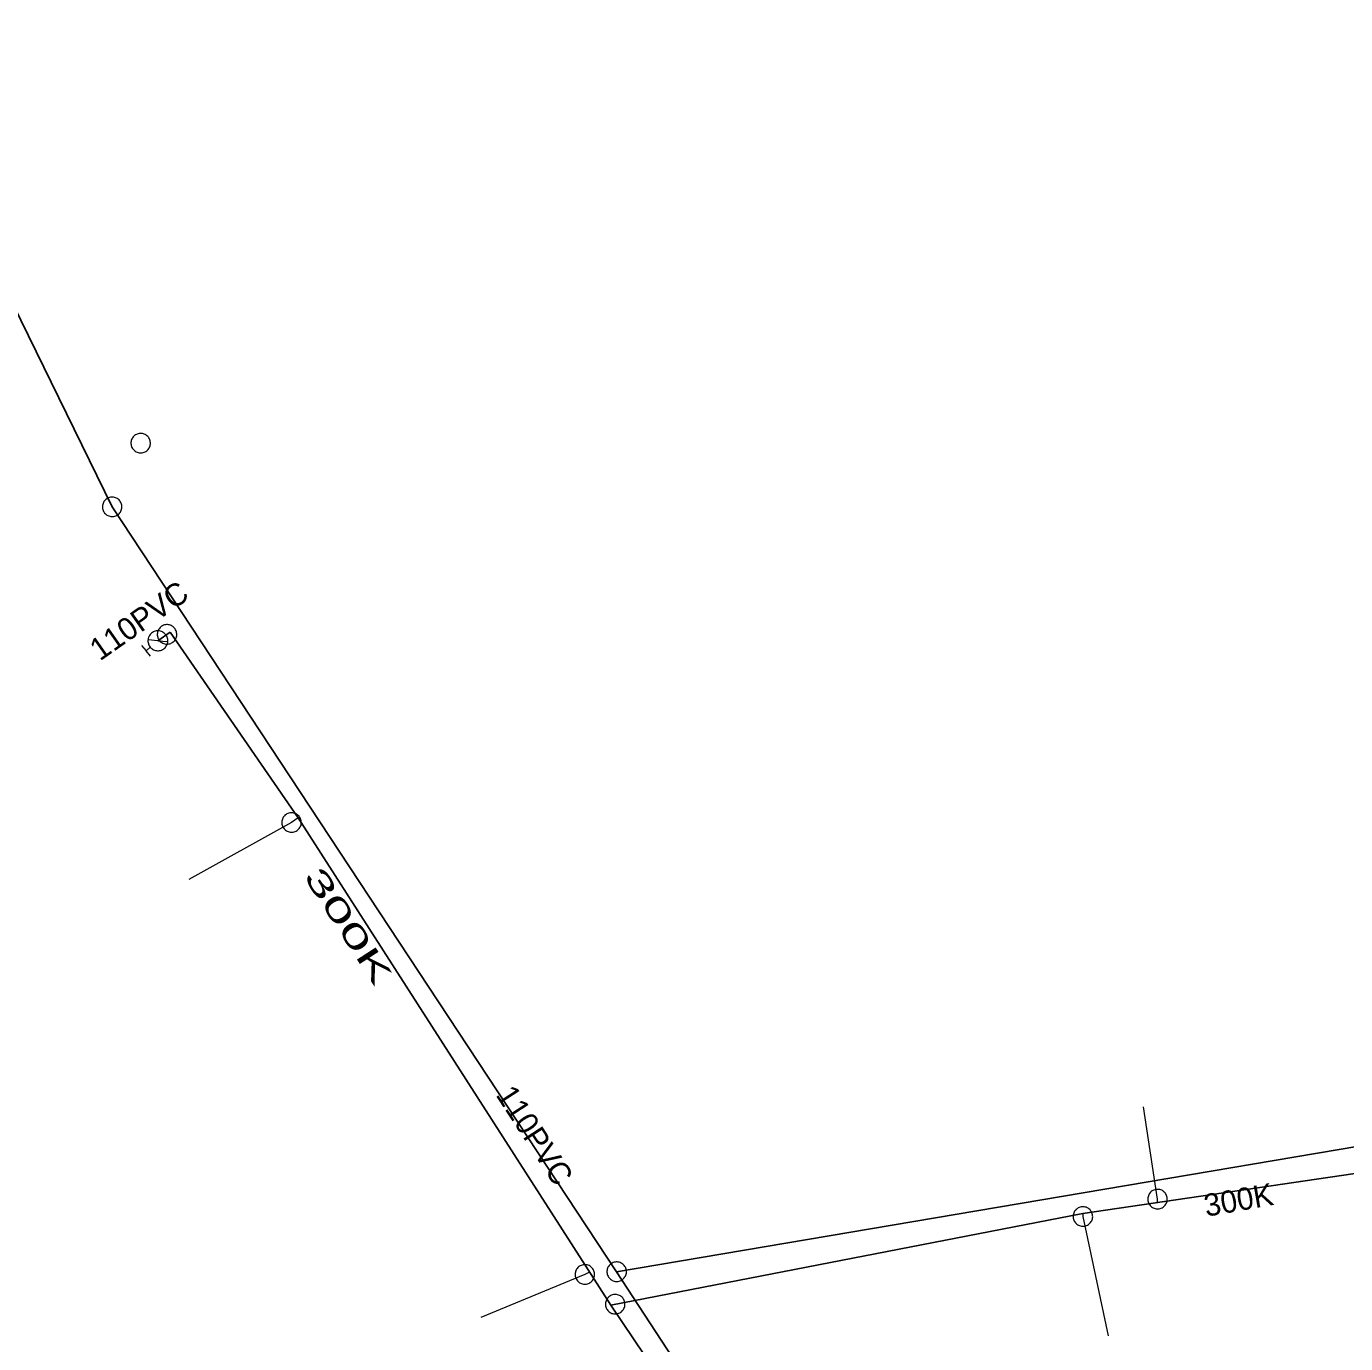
# Model space of a CAD drawing. Extents: x -741806 to -738704, y -1059275 to -1055387.
# Drawn here: x -740655.8 to -740596.6, y -1057415.2 to -1057356.1 of the extents above; entities that cross this region are included whole.
import ezdxf

# ---------------------------------------------------------------- set-up
doc = ezdxf.new("R2010")
doc.units = 0
doc.header["$LTSCALE"] = 0.4
for name, color, linetype, lineweight in [('2', 7, 'Continuous', 25), ('21', 7, 'Continuous', 13), ('3', 7, 'Continuous', 13), ('50', 7, 'Continuous', 13), ('51', 7, 'Continuous', 13), ('52', 7, 'Continuous', 25)]:
    doc.layers.add(name, color=color, linetype=linetype, lineweight=lineweight)
doc.layers.add('5', color=7, linetype='Continuous')
doc.layers.add('53', color=7, linetype='Continuous')

msp = doc.modelspace()

# ---------------------------------------------------------------- linework, layer by layer
at = {"layer": '2'}
for points in [[(-740629.3, -1057411.95), (-740651.94, -1057377.629), (-740665.26, -1057350.399)], [(-740483.87, -1057386.129), (-740524.48, -1057393.58), (-740573.109, -1057402.44), (-740629.3, -1057411.95)], [(-740551.37, -1057549.6), (-740573.489, -1057504.53), (-740597.07, -1057461.26), (-740629.3, -1057411.95)]]:
    msp.add_lwpolyline(points, dxfattribs=at)
at = {"layer": '21'}
for points in [[(-740643.596, -1057391.587), (-740643.89, -1057391.79), (-740648.499, -1057394.343)], [(-740605.036, -1057408.848), (-740605.03, -1057408.69), (-740605.666, -1057404.549)], [(-740608.386, -1057409.341), (-740608.379, -1057409.47), (-740607.25, -1057414.818)], [(-740630.515, -1057411.972), (-740630.73, -1057412.07), (-740635.388, -1057414.007)]]:
    msp.add_lwpolyline(points, dxfattribs=at)
at = {"layer": '3'}
for points in [[(-740650.892, -1057374.399), (-740650.929, -1057374.425), (-740650.963, -1057374.455), (-740650.995, -1057374.489), (-740651.022, -1057374.525), (-740651.045, -1057374.565), (-740651.065, -1057374.607), (-740651.079, -1057374.65), (-740651.09, -1057374.694), (-740651.095, -1057374.74), (-740651.096, -1057374.785), (-740651.092, -1057374.831), (-740651.083, -1057374.877), (-740651.069, -1057374.92), (-740651.052, -1057374.962), (-740651.029, -1057375.002), (-740651.003, -1057375.04), (-740650.972, -1057375.074), (-740650.939, -1057375.105), (-740650.902, -1057375.132), (-740650.862, -1057375.156), (-740650.821, -1057375.175), (-740650.779, -1057375.189), (-740650.733, -1057375.2), (-740650.688, -1057375.206), (-740650.642, -1057375.206), (-740650.596, -1057375.201), (-740650.552, -1057375.193), (-740650.507, -1057375.179), (-740650.465, -1057375.161), (-740650.425, -1057375.139), (-740650.388, -1057375.113), (-740650.354, -1057375.083), (-740650.322, -1057375.049), (-740650.295, -1057375.012), (-740650.272, -1057374.973), (-740650.252, -1057374.931), (-740650.238, -1057374.888), (-740650.228, -1057374.843), (-740650.223, -1057374.798), (-740650.222, -1057374.753), (-740650.226, -1057374.707), (-740650.234, -1057374.661), (-740650.248, -1057374.618), (-740650.266, -1057374.576), (-740650.288, -1057374.536), (-740650.315, -1057374.498), (-740650.345, -1057374.464), (-740650.378, -1057374.433), (-740650.415, -1057374.405), (-740650.455, -1057374.382), (-740650.496, -1057374.363), (-740650.539, -1057374.348), (-740650.584, -1057374.338), (-740650.629, -1057374.332), (-740650.676, -1057374.332), (-740650.722, -1057374.336), (-740650.766, -1057374.345), (-740650.81, -1057374.359), (-740650.852, -1057374.377), (-740650.892, -1057374.398)], [(-740652.18, -1057377.263), (-740652.216, -1057377.29), (-740652.25, -1057377.321), (-740652.281, -1057377.355), (-740652.307, -1057377.392), (-740652.33, -1057377.432), (-740652.349, -1057377.474), (-740652.362, -1057377.518), (-740652.372, -1057377.563), (-740652.375, -1057377.608), (-740652.375, -1057377.654), (-740652.37, -1057377.699), (-740652.361, -1057377.745), (-740652.346, -1057377.787), (-740652.328, -1057377.829), (-740652.304, -1057377.869), (-740652.277, -1057377.906), (-740652.245, -1057377.939), (-740652.212, -1057377.97), (-740652.174, -1057377.997), (-740652.134, -1057378.019), (-740652.092, -1057378.037), (-740652.05, -1057378.051), (-740652.004, -1057378.06), (-740651.959, -1057378.065), (-740651.912, -1057378.065), (-740651.867, -1057378.059), (-740651.823, -1057378.05), (-740651.779, -1057378.035), (-740651.737, -1057378.016), (-740651.698, -1057377.992), (-740651.661, -1057377.966), (-740651.627, -1057377.935), (-740651.596, -1057377.901), (-740651.57, -1057377.863), (-740651.548, -1057377.824), (-740651.529, -1057377.782), (-740651.516, -1057377.738), (-740651.506, -1057377.692), (-740651.502, -1057377.648), (-740651.502, -1057377.602), (-740651.507, -1057377.557), (-740651.517, -1057377.511), (-740651.531, -1057377.468), (-740651.55, -1057377.427), (-740651.573, -1057377.387), (-740651.6, -1057377.35), (-740651.631, -1057377.316), (-740651.665, -1057377.286), (-740651.703, -1057377.259), (-740651.743, -1057377.237), (-740651.785, -1057377.219), (-740651.828, -1057377.204), (-740651.873, -1057377.196), (-740651.919, -1057377.191), (-740651.965, -1057377.191), (-740652.011, -1057377.196), (-740652.055, -1057377.206), (-740652.099, -1057377.221), (-740652.14, -1057377.24), (-740652.179, -1057377.262)], [(-740629.539, -1057411.583), (-740629.575, -1057411.61), (-740629.609, -1057411.64), (-740629.64, -1057411.675), (-740629.666, -1057411.711), (-740629.689, -1057411.751), (-740629.708, -1057411.794), (-740629.721, -1057411.837), (-740629.731, -1057411.882), (-740629.735, -1057411.927), (-740629.735, -1057411.973), (-740629.73, -1057412.019), (-740629.721, -1057412.064), (-740629.706, -1057412.107), (-740629.688, -1057412.149), (-740629.665, -1057412.188), (-740629.638, -1057412.226), (-740629.607, -1057412.259), (-740629.573, -1057412.29), (-740629.536, -1057412.317), (-740629.496, -1057412.339), (-740629.454, -1057412.357), (-740629.411, -1057412.371), (-740629.366, -1057412.381), (-740629.321, -1057412.386), (-740629.274, -1057412.386), (-740629.229, -1057412.38), (-740629.184, -1057412.371), (-740629.14, -1057412.357), (-740629.099, -1057412.338), (-740629.059, -1057412.314), (-740629.023, -1057412.288), (-740628.989, -1057412.258), (-740628.958, -1057412.223), (-740628.931, -1057412.185), (-740628.908, -1057412.147), (-740628.889, -1057412.104), (-740628.876, -1057412.061), (-740628.866, -1057412.015), (-740628.862, -1057411.971), (-740628.862, -1057411.925), (-740628.867, -1057411.879), (-740628.876, -1057411.834), (-740628.89, -1057411.791), (-740628.909, -1057411.749), (-740628.932, -1057411.71), (-740628.959, -1057411.672), (-740628.99, -1057411.638), (-740629.024, -1057411.608), (-740629.062, -1057411.581), (-740629.102, -1057411.559), (-740629.143, -1057411.54), (-740629.187, -1057411.526), (-740629.232, -1057411.517), (-740629.277, -1057411.512), (-740629.323, -1057411.512), (-740629.369, -1057411.517), (-740629.413, -1057411.527), (-740629.457, -1057411.541), (-740629.499, -1057411.56), (-740629.538, -1057411.582)]]:
    msp.add_lwpolyline(points, dxfattribs=at)
at = {"layer": '50'}
for p, q in [((-740650.617, -1057383.85), (-740650.42, -1057384.085)), ((-740650.228, -1057383.924), (-740650.42, -1057384.085)), ((-740649.886, -1057383.636), (-740650.328, -1057383.595)), ((-740649.886, -1057383.636), (-740649.439, -1057383.675)), ((-740650.222, -1057384.321), (-740650.42, -1057384.085))]:
    msp.add_line(p, q, dxfattribs=at)
msp.add_lwpolyline([(-740650.168, -1057383.293), (-740650.204, -1057383.327), (-740650.236, -1057383.36), (-740650.263, -1057383.4), (-740650.285, -1057383.44), (-740650.303, -1057383.481), (-740650.317, -1057383.528), (-740650.326, -1057383.572), (-740650.331, -1057383.62), (-740650.332, -1057383.666), (-740650.324, -1057383.712), (-740650.315, -1057383.758), (-740650.302, -1057383.803), (-740650.28, -1057383.845), (-740650.256, -1057383.885), (-740650.229, -1057383.922), (-740650.197, -1057383.955), (-740650.164, -1057383.987), (-740650.125, -1057384.014), (-740650.084, -1057384.036), (-740650.04, -1057384.056), (-740649.996, -1057384.069), (-740649.95, -1057384.079), (-740649.904, -1057384.083), (-740649.858, -1057384.082), (-740649.81, -1057384.077), (-740649.765, -1057384.068), (-740649.722, -1057384.052), (-740649.677, -1057384.034), (-740649.639, -1057384.008), (-740649.6, -1057383.983), (-740649.565, -1057383.95), (-740649.535, -1057383.914), (-740649.509, -1057383.878), (-740649.484, -1057383.836), (-740649.467, -1057383.793), (-740649.452, -1057383.749), (-740649.444, -1057383.703), (-740649.438, -1057383.656), (-740649.439, -1057383.608), (-740649.445, -1057383.563), (-740649.456, -1057383.516), (-740649.472, -1057383.473), (-740649.488, -1057383.431), (-740649.514, -1057383.389), (-740649.541, -1057383.351), (-740649.573, -1057383.318), (-740649.609, -1057383.288), (-740649.647, -1057383.26), (-740649.687, -1057383.237), (-740649.731, -1057383.218), (-740649.774, -1057383.205), (-740649.821, -1057383.195), (-740649.866, -1057383.191), (-740649.912, -1057383.19), (-740649.959, -1057383.198), (-740650.005, -1057383.206), (-740650.05, -1057383.221), (-740650.091, -1057383.242), (-740650.131, -1057383.266)], close=True, dxfattribs=at)
at = {"layer": '51'}
for points in [[(-740649.757, -1057383.014), (-740649.79, -1057383.045), (-740649.82, -1057383.079), (-740649.847, -1057383.117), (-740649.869, -1057383.157), (-740649.887, -1057383.199), (-740649.901, -1057383.243), (-740649.909, -1057383.288), (-740649.913, -1057383.334), (-740649.912, -1057383.379), (-740649.906, -1057383.424), (-740649.896, -1057383.469), (-740649.882, -1057383.513), (-740649.862, -1057383.555), (-740649.839, -1057383.594), (-740649.811, -1057383.63), (-740649.78, -1057383.664), (-740649.745, -1057383.694), (-740649.708, -1057383.72), (-740649.667, -1057383.742), (-740649.625, -1057383.76), (-740649.581, -1057383.773), (-740649.537, -1057383.783), (-740649.491, -1057383.786), (-740649.445, -1057383.786), (-740649.399, -1057383.78), (-740649.355, -1057383.769), (-740649.312, -1057383.755), (-740649.27, -1057383.735), (-740649.231, -1057383.711), (-740649.194, -1057383.684), (-740649.161, -1057383.653), (-740649.131, -1057383.619), (-740649.105, -1057383.58), (-740649.083, -1057383.541), (-740649.065, -1057383.499), (-740649.051, -1057383.455), (-740649.043, -1057383.41), (-740649.038, -1057383.364), (-740649.04, -1057383.319), (-740649.045, -1057383.273), (-740649.055, -1057383.228), (-740649.07, -1057383.185), (-740649.09, -1057383.144), (-740649.113, -1057383.104), (-740649.141, -1057383.068), (-740649.172, -1057383.034), (-740649.207, -1057383.004), (-740649.243, -1057382.978), (-740649.284, -1057382.956), (-740649.327, -1057382.938), (-740649.37, -1057382.925), (-740649.415, -1057382.915), (-740649.461, -1057382.912), (-740649.506, -1057382.912), (-740649.552, -1057382.918), (-740649.597, -1057382.928), (-740649.639, -1057382.943), (-740649.682, -1057382.963), (-740649.72, -1057382.986), (-740649.756, -1057383.014)], [(-740644.17, -1057391.454), (-740644.203, -1057391.485), (-740644.233, -1057391.519), (-740644.26, -1057391.557), (-740644.282, -1057391.597), (-740644.3, -1057391.639), (-740644.314, -1057391.683), (-740644.322, -1057391.728), (-740644.326, -1057391.774), (-740644.325, -1057391.819), (-740644.319, -1057391.864), (-740644.309, -1057391.909), (-740644.295, -1057391.953), (-740644.275, -1057391.995), (-740644.252, -1057392.034), (-740644.224, -1057392.07), (-740644.193, -1057392.104), (-740644.158, -1057392.134), (-740644.121, -1057392.16), (-740644.08, -1057392.182), (-740644.038, -1057392.2), (-740643.994, -1057392.213), (-740643.95, -1057392.223), (-740643.904, -1057392.226), (-740643.858, -1057392.226), (-740643.812, -1057392.22), (-740643.768, -1057392.209), (-740643.725, -1057392.195), (-740643.683, -1057392.175), (-740643.644, -1057392.151), (-740643.607, -1057392.124), (-740643.574, -1057392.093), (-740643.544, -1057392.059), (-740643.518, -1057392.02), (-740643.496, -1057391.981), (-740643.478, -1057391.939), (-740643.464, -1057391.895), (-740643.456, -1057391.85), (-740643.451, -1057391.804), (-740643.453, -1057391.759), (-740643.458, -1057391.713), (-740643.468, -1057391.668), (-740643.483, -1057391.625), (-740643.503, -1057391.584), (-740643.526, -1057391.544), (-740643.554, -1057391.508), (-740643.585, -1057391.474), (-740643.62, -1057391.444), (-740643.656, -1057391.418), (-740643.697, -1057391.396), (-740643.74, -1057391.378), (-740643.783, -1057391.365), (-740643.828, -1057391.355), (-740643.874, -1057391.352), (-740643.919, -1057391.352), (-740643.965, -1057391.358), (-740644.01, -1057391.368), (-740644.052, -1057391.383), (-740644.095, -1057391.403), (-740644.133, -1057391.426), (-740644.169, -1057391.454)], [(-740605.31, -1057408.354), (-740605.343, -1057408.385), (-740605.373, -1057408.419), (-740605.4, -1057408.457), (-740605.422, -1057408.497), (-740605.44, -1057408.539), (-740605.454, -1057408.583), (-740605.462, -1057408.628), (-740605.466, -1057408.674), (-740605.465, -1057408.719), (-740605.459, -1057408.764), (-740605.449, -1057408.809), (-740605.435, -1057408.853), (-740605.415, -1057408.895), (-740605.392, -1057408.934), (-740605.364, -1057408.97), (-740605.333, -1057409.004), (-740605.298, -1057409.034), (-740605.261, -1057409.06), (-740605.22, -1057409.082), (-740605.178, -1057409.1), (-740605.134, -1057409.113), (-740605.09, -1057409.123), (-740605.044, -1057409.126), (-740604.998, -1057409.126), (-740604.952, -1057409.12), (-740604.908, -1057409.109), (-740604.865, -1057409.095), (-740604.823, -1057409.075), (-740604.784, -1057409.051), (-740604.747, -1057409.024), (-740604.714, -1057408.993), (-740604.684, -1057408.959), (-740604.658, -1057408.92), (-740604.636, -1057408.881), (-740604.618, -1057408.839), (-740604.604, -1057408.795), (-740604.596, -1057408.75), (-740604.591, -1057408.704), (-740604.593, -1057408.659), (-740604.598, -1057408.613), (-740604.608, -1057408.568), (-740604.623, -1057408.525), (-740604.643, -1057408.484), (-740604.666, -1057408.444), (-740604.694, -1057408.408), (-740604.725, -1057408.374), (-740604.76, -1057408.344), (-740604.796, -1057408.318), (-740604.837, -1057408.296), (-740604.88, -1057408.278), (-740604.923, -1057408.265), (-740604.968, -1057408.255), (-740605.014, -1057408.252), (-740605.059, -1057408.252), (-740605.105, -1057408.258), (-740605.15, -1057408.268), (-740605.192, -1057408.283), (-740605.235, -1057408.303), (-740605.273, -1057408.326), (-740605.309, -1057408.354)], [(-740608.659, -1057409.134), (-740608.692, -1057409.165), (-740608.722, -1057409.199), (-740608.749, -1057409.237), (-740608.771, -1057409.277), (-740608.789, -1057409.319), (-740608.803, -1057409.363), (-740608.811, -1057409.408), (-740608.815, -1057409.454), (-740608.814, -1057409.499), (-740608.808, -1057409.544), (-740608.798, -1057409.589), (-740608.784, -1057409.633), (-740608.764, -1057409.675), (-740608.741, -1057409.714), (-740608.713, -1057409.75), (-740608.682, -1057409.784), (-740608.647, -1057409.814), (-740608.61, -1057409.84), (-740608.569, -1057409.862), (-740608.527, -1057409.88), (-740608.483, -1057409.893), (-740608.439, -1057409.903), (-740608.393, -1057409.906), (-740608.347, -1057409.906), (-740608.301, -1057409.9), (-740608.257, -1057409.889), (-740608.214, -1057409.875), (-740608.172, -1057409.855), (-740608.133, -1057409.831), (-740608.096, -1057409.804), (-740608.063, -1057409.773), (-740608.033, -1057409.739), (-740608.007, -1057409.7), (-740607.985, -1057409.661), (-740607.967, -1057409.619), (-740607.953, -1057409.575), (-740607.945, -1057409.53), (-740607.94, -1057409.484), (-740607.942, -1057409.439), (-740607.947, -1057409.393), (-740607.957, -1057409.348), (-740607.972, -1057409.305), (-740607.992, -1057409.264), (-740608.015, -1057409.224), (-740608.043, -1057409.188), (-740608.074, -1057409.154), (-740608.109, -1057409.124), (-740608.145, -1057409.098), (-740608.186, -1057409.076), (-740608.229, -1057409.058), (-740608.272, -1057409.045), (-740608.317, -1057409.035), (-740608.363, -1057409.032), (-740608.408, -1057409.032), (-740608.454, -1057409.038), (-740608.499, -1057409.048), (-740608.541, -1057409.063), (-740608.584, -1057409.083), (-740608.622, -1057409.106), (-740608.658, -1057409.134)], [(-740631.01, -1057411.734), (-740631.043, -1057411.765), (-740631.073, -1057411.799), (-740631.1, -1057411.837), (-740631.122, -1057411.877), (-740631.14, -1057411.919), (-740631.154, -1057411.963), (-740631.162, -1057412.008), (-740631.166, -1057412.054), (-740631.165, -1057412.099), (-740631.159, -1057412.144), (-740631.149, -1057412.189), (-740631.135, -1057412.233), (-740631.115, -1057412.275), (-740631.092, -1057412.314), (-740631.064, -1057412.35), (-740631.033, -1057412.384), (-740630.998, -1057412.414), (-740630.961, -1057412.44), (-740630.92, -1057412.462), (-740630.878, -1057412.48), (-740630.834, -1057412.493), (-740630.79, -1057412.503), (-740630.744, -1057412.506), (-740630.698, -1057412.506), (-740630.652, -1057412.5), (-740630.608, -1057412.489), (-740630.565, -1057412.475), (-740630.523, -1057412.455), (-740630.484, -1057412.431), (-740630.447, -1057412.404), (-740630.414, -1057412.373), (-740630.384, -1057412.339), (-740630.358, -1057412.3), (-740630.336, -1057412.261), (-740630.318, -1057412.219), (-740630.304, -1057412.175), (-740630.296, -1057412.13), (-740630.291, -1057412.084), (-740630.293, -1057412.039), (-740630.298, -1057411.993), (-740630.308, -1057411.948), (-740630.323, -1057411.905), (-740630.343, -1057411.864), (-740630.366, -1057411.824), (-740630.394, -1057411.788), (-740630.425, -1057411.754), (-740630.46, -1057411.724), (-740630.496, -1057411.698), (-740630.537, -1057411.676), (-740630.58, -1057411.658), (-740630.623, -1057411.645), (-740630.668, -1057411.635), (-740630.714, -1057411.632), (-740630.759, -1057411.632), (-740630.805, -1057411.638), (-740630.85, -1057411.648), (-740630.892, -1057411.663), (-740630.935, -1057411.683), (-740630.973, -1057411.706), (-740631.009, -1057411.734)], [(-740629.645, -1057413.071), (-740629.678, -1057413.102), (-740629.708, -1057413.136), (-740629.735, -1057413.174), (-740629.757, -1057413.214), (-740629.775, -1057413.256), (-740629.789, -1057413.3), (-740629.797, -1057413.345), (-740629.801, -1057413.391), (-740629.8, -1057413.436), (-740629.794, -1057413.481), (-740629.784, -1057413.526), (-740629.77, -1057413.57), (-740629.75, -1057413.612), (-740629.727, -1057413.651), (-740629.699, -1057413.687), (-740629.668, -1057413.721), (-740629.633, -1057413.751), (-740629.596, -1057413.777), (-740629.555, -1057413.799), (-740629.513, -1057413.817), (-740629.469, -1057413.83), (-740629.425, -1057413.84), (-740629.379, -1057413.843), (-740629.333, -1057413.843), (-740629.287, -1057413.837), (-740629.243, -1057413.826), (-740629.2, -1057413.812), (-740629.158, -1057413.792), (-740629.119, -1057413.768), (-740629.082, -1057413.741), (-740629.049, -1057413.71), (-740629.019, -1057413.676), (-740628.993, -1057413.637), (-740628.971, -1057413.598), (-740628.953, -1057413.556), (-740628.939, -1057413.512), (-740628.931, -1057413.467), (-740628.926, -1057413.421), (-740628.928, -1057413.376), (-740628.933, -1057413.33), (-740628.943, -1057413.285), (-740628.958, -1057413.242), (-740628.978, -1057413.201), (-740629.001, -1057413.161), (-740629.029, -1057413.125), (-740629.06, -1057413.091), (-740629.095, -1057413.061), (-740629.131, -1057413.035), (-740629.172, -1057413.013), (-740629.215, -1057412.995), (-740629.258, -1057412.982), (-740629.303, -1057412.972), (-740629.349, -1057412.969), (-740629.394, -1057412.969), (-740629.44, -1057412.975), (-740629.485, -1057412.985), (-740629.527, -1057413), (-740629.57, -1057413.02), (-740629.608, -1057413.043), (-740629.644, -1057413.071)]]:
    msp.add_lwpolyline(points, dxfattribs=at)
at = {"layer": '52'}
msp.add_line((-740649.339, -1057383.253), (-740649.89, -1057383.639), dxfattribs=at)
for points in [[(-740629.568, -1057413.446), (-740643.596, -1057391.587), (-740649.339, -1057383.253)], [(-740447.059, -1057384.081), (-740482.611, -1057386.857), (-740514.765, -1057392.747), (-740521.043, -1057394.158), (-740540.033, -1057397.307), (-740548.526, -1057398.619), (-740563.186, -1057401.392), (-740569.092, -1057402.71), (-740590.765, -1057406.389), (-740595.761, -1057407.486), (-740608.386, -1057409.341), (-740629.568, -1057413.446)], [(-740629.568, -1057413.446), (-740618.379, -1057430.067), (-740601.454, -1057456.58), (-740598.046, -1057461.412), (-740591.452, -1057473.831), (-740582.381, -1057489.777), (-740580.548, -1057493.651), (-740578.601, -1057497.165), (-740575.153, -1057503.61), (-740568.886, -1057515.331), (-740551.89, -1057550.899), (-740551.756, -1057567.162), (-740551.934, -1057571.904)]]:
    msp.add_lwpolyline(points, dxfattribs=at)

# ---------------------------------------------------------------- texts
at = {"layer": '5', "width": 1.9}
msp.add_text('300K', height=1, rotation=303, dxfattribs=at).set_placement((-740643.377, -1057394.212))
at = {"layer": '5'}
msp.add_text('300K', height=1, rotation=10, dxfattribs=at).set_placement((-740602.845, -1057409.485))
at = {"layer": '53'}
for rotation, p in [(35, (-740652.491, -1057384.568)), (303, (-740634.752, -1057404.008))]:
    msp.add_text('110PVC', height=1, rotation=rotation, dxfattribs=at).set_placement(p)

doc.saveas('drawing.dxf')
